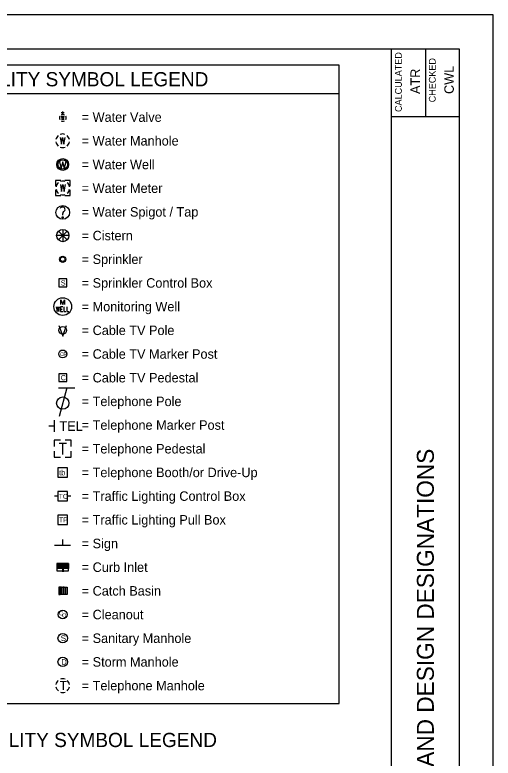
# Model space of a CAD drawing. Extents: x 0 to 34, y 0 to 22.
# Drawn here: x 26.94 to 34, y 11.02 to 22 of the extents above; entities that cross this region are included whole.
import ezdxf

# ---------------------------------------------------------------- set-up
doc = ezdxf.new("R2010")
doc.units = 0
for name, color, linetype in [('Default', 7, 'Continuous'), ('SH_Border', 7, 'Continuous'), ('SH_Cut_Line', 7, 'Continuous'), ('SH_Data', 7, 'Continuous'), ('SH_Text', 7, 'Continuous'), ('UT_X_Electric', 7, 'Continuous'), ('UT_X_Water_Cells', 7, 'Continuous')]:
    doc.layers.add(name, color=color, linetype=linetype)

# ---------------------------------------------------------------- blocks, each defined once
blk = doc.blocks.new('POINT_DISPLAY')
at = {"layer": 'Default'}
blk.add_line((0, 0), (0, 0), dxfattribs=at)
blk = doc.blocks.new('uobj')
at = {"layer": 'Default'}
blk.add_line((0, -0.0272), (0, -0.0101), dxfattribs=at)
for centre, radius in [((0, 0), 0.072), ((0, -0.0508), 0.00613)]:
    blk.add_circle(centre, radius, dxfattribs=at)
for centre, radius, start, end in [((-0.0023, 0.0292), 0.0271, 88.32401, 152.53853), ((-0.0004, 0.0316), 0.0248, 291.93294, 92.45835), ((0.0211, -0.0086), 0.0211, 125.46179, 184.08291)]:
    blk.add_arc(centre, radius, start, end, dxfattribs=at)
blk = doc.blocks.new('wgv')
at = {"layer": 'Default'}
for p, q in [((0.032, 0.102), (-0.032, 0.102)), ((0, 0.07), (0, 0.134))]:
    blk.add_line(p, q, dxfattribs=at)
blk.add_lwpolyline([(-0.032, 0.041), (-0.016, -0.045), (0, 0.041), (0.016, -0.045), (0.032, 0.041)], dxfattribs=at)
for start, end in [(150.0184, 209.9816), (60.0184, 120.0157), (330.0184, 29.9816), (239.9843, 299.9816)]:
    blk.add_arc((0, 0), 0.07, start, end, dxfattribs=at)
blk.add_blockref('POINT_DISPLAY', (0, 0), dxfattribs=at)
blk = doc.blocks.new('CISTERN')
at = {"layer": 'Default'}
for p, q in [((0.0648, 0), (-0.0648, 0)), ((0.0458, -0.0458), (-0.0458, 0.0458)), ((-0.0458, -0.0458), (0.0458, 0.0458)), ((0, 0.0648), (0, -0.0648))]:
    blk.add_line(p, q, dxfattribs=at)
blk.add_circle((0, 0), 0.0648, dxfattribs=at)
blk = doc.blocks.new('SPRINKLER')
at = {"layer": 'Default'}
for radius in [0.0329, 0.0239]:
    blk.add_circle((0, 0), radius, dxfattribs=at)
blk = doc.blocks.new('SPCB')
at = {"layer": 'Default'}
for p, q in [((0.0418, 0.0418), (-0.0418, 0.0418)), ((-0.0418, 0.0418), (-0.0418, -0.0418)), ((0.0418, -0.0418), (0.0418, 0.0418)), ((-0.0418, -0.0418), (0.0418, -0.0418))]:
    blk.add_line(p, q, dxfattribs=at)
blk.add_text('S', height=0.0555, dxfattribs=at).set_placement((-0.021, -0.0279))
blk = doc.blocks.new('CP')
at = {"layer": 'Default'}
blk.add_lwpolyline([(-0.0396, 0.0507), (0, -0.0625), (0.0396, 0.0507)], dxfattribs=at)
blk.add_circle((0, 0), 0.0406, dxfattribs=at)
blk = doc.blocks.new('MWELL')
at = {"layer": 'Default'}
blk.add_line((-0.0233, -0.0258), (-0.0045, -0.0258), dxfattribs=at)
for points in [[(-0.0185, 0.023), (-0.0185, 0.073), (0, 0.023), (0.0185, 0.073), (0.0185, 0.023)], [(-0.0696, -0.0008), (-0.0604, -0.0508), (-0.0511, -0.0008), (-0.0419, -0.0508), (-0.0326, -0.0008)], [(0.0017, -0.0008), (-0.0233, -0.0008), (-0.0233, -0.0508), (0.0017, -0.0508)], [(0.0122, -0.0008), (0.0122, -0.0508), (0.0334, -0.0508)], [(0.0445, -0.0008), (0.0445, -0.0508), (0.0658, -0.0508)]]:
    blk.add_lwpolyline(points, dxfattribs=at)
blk.add_circle((0, 0), 0.0937, dxfattribs=at)
blk = doc.blocks.new('WWELL')
at = {"layer": 'Default'}
blk.add_lwpolyline([(-0.0353, 0.0267), (-0.0162, -0.0406), (0.0001, 0.0169), (0.0162, -0.0409), (0.0352, 0.0267), (0.0322, 0.0265), (0.0164, -0.031), (0.0001, 0.0268), (-0.0158, -0.031), (-0.0321, 0.0267)], close=True, dxfattribs=at)
for radius in [0.0625, 0.05]:
    blk.add_circle((0, 0), radius, dxfattribs=at)
blk = doc.blocks.new('CPED')
at = {"layer": 'Default'}
for p, q in [((-0.0418, 0.0418), (-0.0418, -0.0418)), ((0.0418, 0.0418), (-0.0418, 0.0418)), ((0.0418, -0.0418), (0.0418, 0.0418)), ((-0.0418, -0.0418), (0.0418, -0.0418))]:
    blk.add_line(p, q, dxfattribs=at)
blk.add_text('C', height=0.0555, dxfattribs=at).set_placement((-0.021, -0.0279))
blk = doc.blocks.new('tped')
at = {"layer": 'Default'}
for p, q in [((-0.0392, 0.0602), (0.0392, 0.0602)), ((0, -0.0602), (0, 0.0602))]:
    blk.add_line(p, q, dxfattribs=at)
for points in [[(-0.0241, 0.0904), (-0.0904, 0.0904), (-0.0904, 0.0241)], [(0.0904, 0.0241), (0.0904, 0.0904), (0.0241, 0.0904)], [(-0.0904, -0.0241), (-0.0904, -0.0904), (-0.0241, -0.0904)], [(0.0241, -0.0904), (0.0904, -0.0904), (0.0904, -0.0241)]]:
    blk.add_lwpolyline(points, dxfattribs=at)
blk.add_blockref('POINT_DISPLAY', (0, 0), dxfattribs=at)
blk = doc.blocks.new('TB')
at = {"layer": 'Default'}
for p, q in [((0.0501, 0.0501), (-0.0501, 0.0501)), ((-0.0501, 0.0501), (-0.0501, -0.0501)), ((0.0501, -0.0501), (0.0501, 0.0501)), ((-0.0501, -0.0501), (0.0501, -0.0501))]:
    blk.add_line(p, q, dxfattribs=at)
blk.add_text('tb', height=0.05757, dxfattribs=at).set_placement((-0.0379, -0.031))
blk = doc.blocks.new('TCB')
at = {"layer": 'Default'}
for p, q in [((-0.0501, 0), (-0.0861, 0)), ((-0.0501, 0.0487), (-0.0501, -0.0487)), ((0.0501, 0.0487), (-0.0501, 0.0487)), ((0.0501, -0.0487), (0.0501, 0.0487)), ((0.0861, 0), (0.0501, 0)), ((-0.0501, -0.0487), (0.0501, -0.0487))]:
    blk.add_line(p, q, dxfattribs=at)
blk.add_text('TC', height=0.05182, dxfattribs=at).set_placement((-0.0418, -0.0286))
blk = doc.blocks.new('TPB')
at = {"layer": 'Default'}
for p, q in [((0.0501, 0.0501), (-0.0501, 0.0501)), ((-0.0501, 0.0501), (-0.0501, -0.0501)), ((0.0501, -0.0501), (0.0501, 0.0501)), ((-0.0501, -0.0501), (0.0501, -0.0501))]:
    blk.add_line(p, q, dxfattribs=at)
blk.add_text('TP', height=0.05182, dxfattribs=at).set_placement((-0.0388, -0.0264))
blk = doc.blocks.new('CI')
at = {"layer": 'Default'}
for p, q in [((0.0607, 0.0395), (-0.0607, 0.0395)), ((-0.0607, 0.0395), (-0.0607, -0.0395)), ((-0.0596, 0.0395), (-0.0596, -0.0138)), ((-0.0526, 0.0395), (-0.0526, -0.0138)), ((-0.0456, 0.0395), (-0.0456, -0.0138)), ((-0.0386, 0.0395), (-0.0386, -0.0138)), ((-0.0316, 0.0395), (-0.0316, -0.0138)), ((-0.0246, 0.0395), (-0.0246, -0.0138)), ((-0.0176, 0.0395), (-0.0176, -0.0138)), ((-0.0106, 0.0395), (-0.0106, -0.0138)), ((-0.0037, 0.0395), (-0.0036, -0.0138)), ((0.0033, 0.0395), (0.0034, -0.0138)), ((0.0103, 0.0395), (0.0104, -0.0138)), ((0.0173, 0.0395), (0.0174, -0.0138)), ((0.0243, 0.0395), (0.0244, -0.0138)), ((0.0313, 0.0395), (0.0314, -0.0138)), ((0.0383, 0.0395), (0.0384, -0.0137)), ((0.0453, 0.0395), (0.0453, -0.0137)), ((0.0523, 0.0395), (0.0523, -0.0137)), ((0.0593, 0.0395), (0.0593, -0.0137)), ((0.0607, -0.0395), (0.0607, 0.0395)), ((0.0607, -0.0137), (-0.0607, -0.0138)), ((-0.0607, -0.0395), (0.0607, -0.0395)), ((-0.0024, -0.0138), (-0.0024, -0.0493)), ((0.003, -0.0138), (0.003, -0.0493))]:
    blk.add_line(p, q, dxfattribs=at)
blk = doc.blocks.new('CO')
at = {"layer": 'Default'}
blk.add_circle((0, 0), 0.0466, dxfattribs=at)
for s, p in [('C', (-0.0387, -0.009)), ('O', (-0.0072, -0.0304))]:
    blk.add_text(s, height=0.0432, dxfattribs=at).set_placement(p)
blk = doc.blocks.new('CBG')
at = {"layer": 'Default'}
for p, q in [((-0.0419, 0.04), (-0.042, -0.04)), ((-0.014, 0.04), (-0.0419, 0.04)), ((-0.028, 0.04), (0.0297, 0.04)), ((-0.0279, -0.04), (-0.028, 0.04)), ((-0.0139, -0.04), (-0.014, 0.04)), ((-0.0001, 0.04), (0.0001, -0.04)), ((0.0139, 0.04), (-0.0001, 0.04)), ((0.014, -0.04), (0.0139, 0.04)), ((0.0139, 0.04), (0.0453, 0.04)), ((0.0297, 0.04), (0.0297, -0.04)), ((0.0453, 0.04), (0.0453, -0.04)), ((-0.042, -0.04), (-0.0279, -0.04)), ((0.0297, -0.04), (-0.0279, -0.04)), ((0.0001, -0.04), (-0.0139, -0.04)), ((0.0453, -0.04), (0.014, -0.04))]:
    blk.add_line(p, q, dxfattribs=at)
blk = doc.blocks.new('MHSTM')
at = {"layer": 'Default'}
blk.add_circle((0, 0), 0.05, dxfattribs=at)
blk.add_text('D', height=0.06, dxfattribs=at).set_placement((-0.0156, -0.0301))
blk = doc.blocks.new('MHS')
at = {"layer": 'Default'}
blk.add_circle((0, 0), 0.05, dxfattribs=at)
blk.add_text('S', height=0.06, rotation=3.23718, dxfattribs=at).set_placement((-0.0183, -0.0311))
blk = doc.blocks.new('CLM')
at = {"layer": 'Default'}
blk.add_circle((0, 0), 0.0421, dxfattribs=at)
blk.add_text('CP', height=0.03748, dxfattribs=at).set_placement((-0.0302, -0.0214))

msp = doc.modelspace()

# ---------------------------------------------------------------- linework, layer by layer
at = {"layer": 'Default'}
for p, q in [((27.609, 20.189), (27.628, 20.089)), ((27.628, 20.089), (27.646, 20.189)), ((27.646, 20.189), (27.665, 20.089)), ((27.665, 20.089), (27.684, 20.189)), ((27.612, 19.492), (27.631, 19.392)), ((27.631, 19.392), (27.649, 19.492)), ((27.649, 19.492), (27.668, 19.392)), ((27.668, 19.392), (27.686, 19.492)), ((27.587, 16.488), (27.647, 16.488)), ((27.707, 16.488), (27.594, 16.065)), ((27.647, 16.488), (27.707, 16.488)), ((27.707, 16.488), (27.767, 16.488)), ((27.767, 16.488), (27.827, 16.488)), ((27.441, 15.925), (27.525, 15.925)), ((27.525, 15.841), (27.525, 16.009)), ((27.644, 14.246), (27.644, 14.162)), ((27.526, 14.162), (27.761, 14.162))]:
    msp.add_line(p, q, dxfattribs=at)
msp.add_circle((27.647, 16.263), 0.0917, dxfattribs=at)
for centre, start, end in [((27.646, 20.139), 130.0806, 170.0721), ((27.646, 20.139), 70.0577, 110.1061), ((27.646, 20.139), 10.0169, 50.0392), ((27.646, 20.139), 190.0169, 230.0392), ((27.646, 20.139), 310.0114, 350.0264), ((27.646, 20.139), 250.0577, 290.0473), ((27.649, 19.442), 130.0806, 170.0721), ((27.649, 19.442), 70.0577, 110.1061), ((27.649, 19.442), 10.0169, 50.0392), ((27.649, 19.442), 190.0169, 230.0392), ((27.649, 19.442), 250.0577, 290.0473), ((27.649, 19.442), 310.0114, 350.0264), ((27.647, 12.089), 130.0806, 170.0721), ((27.647, 12.089), 70.0577, 110.1061), ((27.647, 12.089), 10.0169, 50.0392), ((27.647, 12.089), 190.0169, 230.0392), ((27.647, 12.089), 250.0577, 290.0473), ((27.647, 12.089), 310.0114, 350.0264)]:
    msp.add_arc(centre, 0.101, start, end, dxfattribs=at)
at = {"layer": 'SH_Border'}
for p, q in [((32.5, 0.5), (32.5, 21.5)), ((33, 21.5), (33, 20.5)), ((32.5, 20.5), (33.5, 20.5))]:
    msp.add_line(p, q, dxfattribs=at)
msp.add_lwpolyline([(2, 21.5), (33.5, 21.5), (33.5, 0.5), (2, 0.5)], close=True, dxfattribs=at)
at = {"layer": 'SH_Cut_Line'}
msp.add_lwpolyline([(0, 0), (34, 0), (34, 22), (0, 22)], close=True, dxfattribs=at)
at = {"layer": 'SH_Text'}
msp.add_line((23.587, 20.839), (31.729, 20.839), dxfattribs=at)
msp.add_lwpolyline([(23.587, 11.826), (31.729, 11.826), (31.729, 21.259), (23.587, 21.259)], close=True, dxfattribs=at)
at = {"layer": 'UT_X_Electric'}
for points in [[(27.62, 19.551), (27.54, 19.551), (27.54, 19.471)], [(27.759, 19.471), (27.759, 19.551), (27.678, 19.551)], [(27.54, 19.413), (27.54, 19.332), (27.62, 19.332)], [(27.678, 19.332), (27.759, 19.332), (27.759, 19.413)]]:
    msp.add_lwpolyline(points, dxfattribs=at)

# ---------------------------------------------------------------- block references
at = {"layer": 'Default'}
for name, p, xscale, yscale in [('wgv', (27.648, 20.479), 0.7000000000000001, 0.7000000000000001), ('POINT_DISPLAY', (27.646, 20.139), 0.07, 0.07), ('WWELL', (27.647, 19.789), 1.4000000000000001, 1.4000000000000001), ('POINT_DISPLAY', (27.649, 19.442), 0.07, 0.07), ('CISTERN', (27.647, 18.739), 1.4000000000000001, 1.4000000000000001), ('SPRINKLER', (27.647, 18.389), 1.4000000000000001, 1.4000000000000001), ('SPCB', (27.647, 18.039), 1.4000000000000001, 1.4000000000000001), ('MWELL', (27.647, 17.689), 1.4000000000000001, 1.4000000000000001), ('CP', (27.647, 17.339), 1.4000000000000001, 1.4000000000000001), ('CLM', (27.647, 16.989), 1.4000000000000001, 1.4000000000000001), ('CPED', (27.647, 16.639), 1.4000000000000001, 1.4000000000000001), ('tped', (27.647, 15.589), 1.4000000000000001, 1.4000000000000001), ('TB', (27.647, 15.239), 1.4000000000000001, 1.4000000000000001), ('TCB', (27.647, 14.889), 1.4000000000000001, 1.4000000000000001), ('TPB', (27.647, 14.539), 1.4000000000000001, 1.4000000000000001), ('CI', (27.647, 13.839), 1.4000000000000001, 1.4000000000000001), ('CBG', (27.647, 13.489), 1.4000000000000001, 1.4000000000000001), ('CO', (27.647, 13.139), 1.4000000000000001, 1.4000000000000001), ('MHS', (27.647, 12.789), 1.4000000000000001, 1.4000000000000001), ('MHSTM', (27.647, 12.439), 1.4000000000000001, 1.4000000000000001), ('POINT_DISPLAY', (27.647, 12.089), 0.07, 0.07)]:
    msp.add_blockref(name, p, dxfattribs=dict(at, xscale=xscale, yscale=yscale))
at = {"layer": 'UT_X_Water_Cells', "xscale": 1.4000000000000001, "yscale": 1.4000000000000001}
msp.add_blockref('uobj', (27.647, 19.08), dxfattribs=at)

# ---------------------------------------------------------------- texts
at = {"layer": 'Default'}
for s, height, p in [('TEL', 0.14, (27.599, 15.853)), ('T', 0.134, (27.602, 12.022))]:
    msp.add_text(s, height=height, dxfattribs=at).set_placement(p)
at = {"layer": 'SH_Data'}
for s, height, p in [('CALCULATED', 0.1, (32.652, 20.565)), ('CHECKED', 0.1, (33.152, 20.708)), ('ATR ', 0.14, (32.92, 20.831)), ('CWL ', 0.14, (33.42, 20.831)), ('PLAN LEGEND AND DESIGN DESIGNATIONS', 0.25, (33.125, 8.456))]:
    msp.add_text(s, height=height, rotation=90, dxfattribs=at).set_placement(p)
at = {"layer": 'SH_Text'}
for s, p in [('EXISTING UTILITY SYMBOL LEGEND', (24.882, 20.944)), ('PROPOSED UTILITY SYMBOL LEGEND', (24.727, 11.181))]:
    msp.add_text(s, height=0.21, rotation=0, dxfattribs=at).set_placement(p)
for s, p in [('= Water Valve', (27.927, 20.419)), ('= Water Manhole', (27.927, 20.069)), ('= Water Well', (27.927, 19.719)), ('= Water Meter', (27.927, 19.369)), ('= Water Spigot / Tap', (27.927, 19.019)), ('= Cistern', (27.927, 18.669)), ('= Sprinkler', (27.927, 18.319)), ('= Sprinkler Control Box', (27.927, 17.969)), ('= Monitoring Well', (27.927, 17.619)), ('= Cable TV Pole', (27.927, 17.269)), ('= Cable TV Marker Post', (27.927, 16.919)), ('= Cable TV Pedestal', (27.927, 16.569)), ('= Telephone Pole', (27.927, 16.219)), ('= Telephone Marker Post', (27.927, 15.869)), ('= Telephone Pedestal', (27.927, 15.519)), ('= Telephone Booth/or Drive-Up', (27.927, 15.169)), ('= Traffic Lighting Control Box', (27.927, 14.819)), ('= Traffic Lighting Pull Box', (27.927, 14.469)), ('= Sign', (27.927, 14.119)), ('= Curb Inlet', (27.927, 13.769)), ('= Catch Basin', (27.927, 13.419)), ('= Cleanout', (27.927, 13.069)), ('= Sanitary Manhole', (27.927, 12.719)), ('= Storm Manhole', (27.927, 12.369)), ('= Telephone Manhole', (27.927, 12.019))]:
    msp.add_text(s, height=0.14, dxfattribs=at).set_placement(p)

doc.saveas('drawing.dxf')
